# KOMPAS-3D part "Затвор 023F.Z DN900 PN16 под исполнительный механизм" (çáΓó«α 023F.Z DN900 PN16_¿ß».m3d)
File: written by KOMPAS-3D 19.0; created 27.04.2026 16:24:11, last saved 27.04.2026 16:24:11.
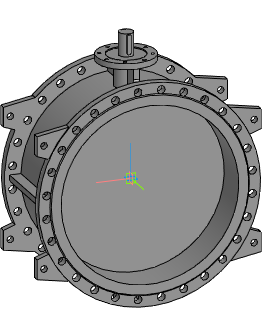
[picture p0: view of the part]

Document properties: Автор: Евгений; Полное имя файла: Z:\3.Личные\kachalov\3d для проектировщиков\1.7 Тип 023F.Z Затвор дисковый поворотный фланцевый с двумя эксцентриками\Затвор 023F.Z DN200-DN1600_исп\_stp_Затвор 023F.Z DN200-DN1600_исп\Затвор 023F.Z DN900 PN16_исп.m3d

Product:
- Part/product: Затвор 023F.Z DN900 PN16 под исполнительный механизм

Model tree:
1. Операция без истории:1  (labels: Затвор 023F.Z DN900 PN16 под исполнительный механизм)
